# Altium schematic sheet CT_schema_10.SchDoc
size 382 x 278 mm
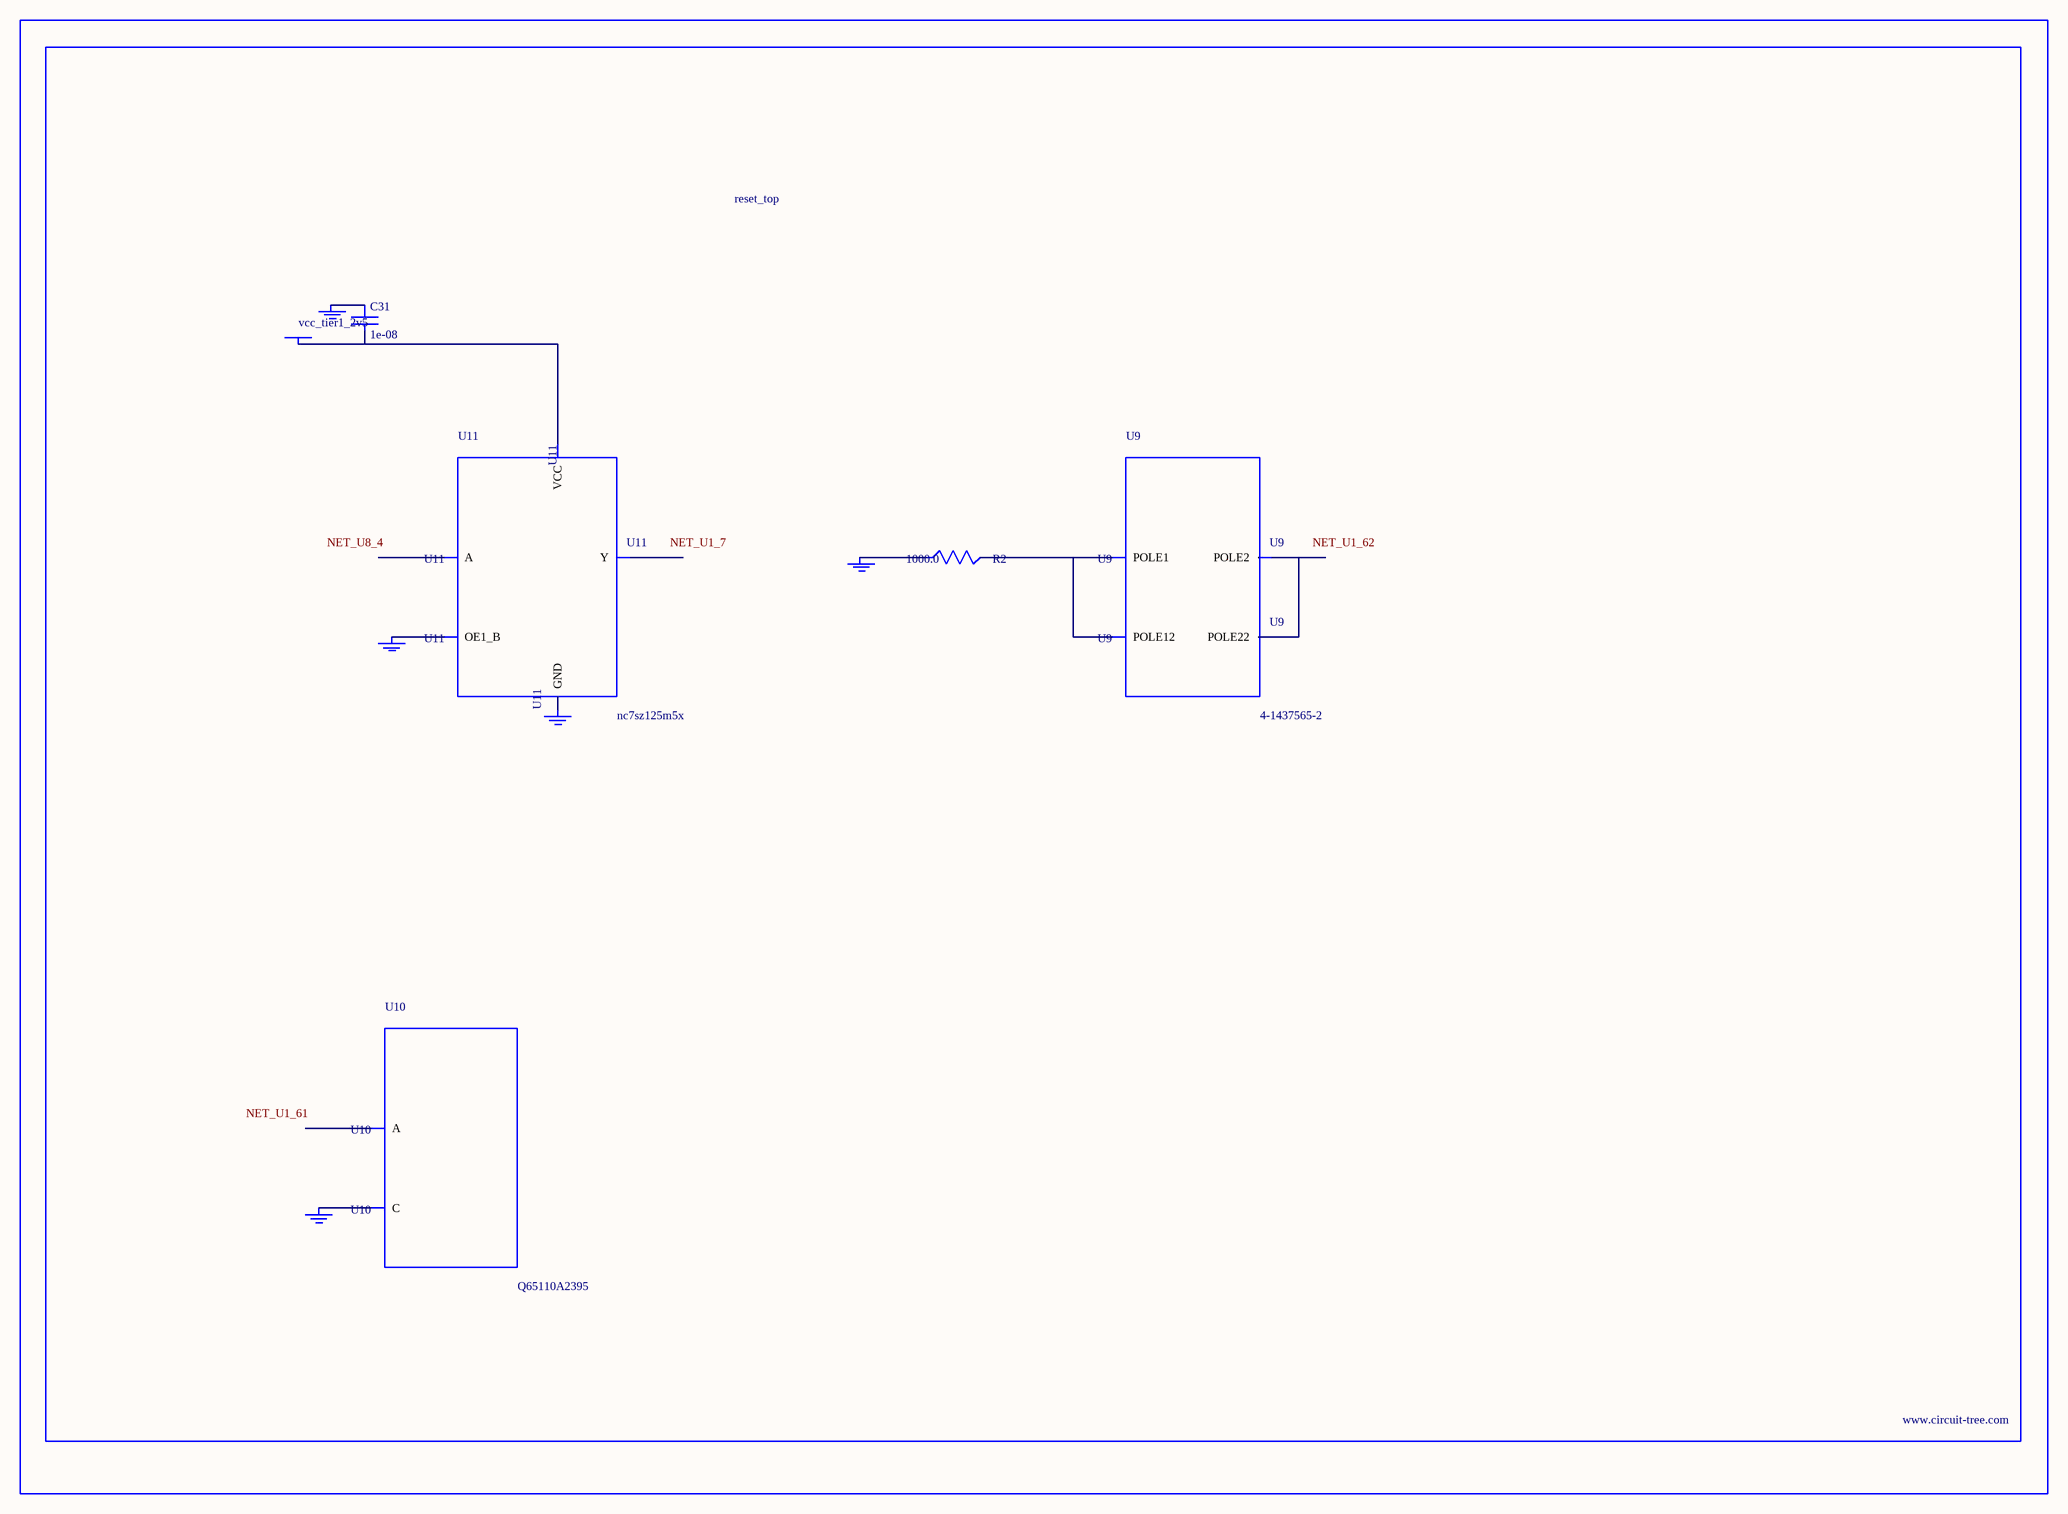
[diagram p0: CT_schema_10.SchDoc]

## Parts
BORDER9  (no value)
C31  1e-08  [C0402]
GND_INSTANCE_9_0  (no value)
GND_INSTANCE_9_1  (no value)
GND_INSTANCE_9_2  (no value)
GND_INSTANCE_9_3  (no value)
GND_INSTANCE_9_4  (no value)
POWER_INSTANCE_9_0  vcc_tier1_2v5
R2  1000.0  [R0603]
U9  4-1437565-2  [SW_4-1437565-2]
U10  Q65110A2395  [LGM67K-G1J2-24-Z]
U11  nc7sz125m5x  [NC7SZ125M5X]

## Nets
NetC31_1: C31.1 GND_INSTANCE_9_2.0(GND)
NetC31_2: C31.2 POWER_INSTANCE_9_0.0(PWR) U11.5(VCC)
NetGND_INSTANCE_9_0_0: GND_INSTANCE_9_0.0(GND) R2.1
NetGND_INSTANCE_9_1_0: GND_INSTANCE_9_1.0(GND) U10.C
NetGND_INSTANCE_9_3_0: GND_INSTANCE_9_3.0(GND) U11.1(OE1_B)
NetGND_INSTANCE_9_4_0: GND_INSTANCE_9_4.0(GND) U11.3(GND)
NetR2_2: R2.2 U9.1(POLE1) U9.2(POLE12)
NetU9_3: U9.3(POLE2) U9.4(POLE22)

Not connected (* = marked no-connect by the designer): U10 A; U11 2(A) 4(Y)

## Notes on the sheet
- Labels drawn without touching a wire or pin: NET_U1_7, NET_U1_61, NET_U1_62, NET_U8_4

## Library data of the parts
BORDER9 = BORDER_PAGE9
C31 = C0402C103K3RAC
GND_INSTANCE_9_0-GND_INSTANCE_9_4 = GND
POWER_INSTANCE_9_0 = PWR
R2 = RC0603JR-071KL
